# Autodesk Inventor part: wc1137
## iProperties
Shininess: 64.0
Length Units: 11272
Angle Units: 11279
Time Units: 11290
Mass Units: 11286
Length Display Precision: 3
Angle Display Precision: 2
Compacted: True
Part Number: wc1137
Document SubType Name: Modeling
Created: 2004-08
Designer: John Blackburn
Manufacturer: Standard
Standards Organization: Custom
Density: 0.0
Volumn: 0.0
Area: 0.0
PropertySet Name: Model Information
Control State: 0
Master: False
Checked Out: False
Author: John Blackburn
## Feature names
1. Base1
